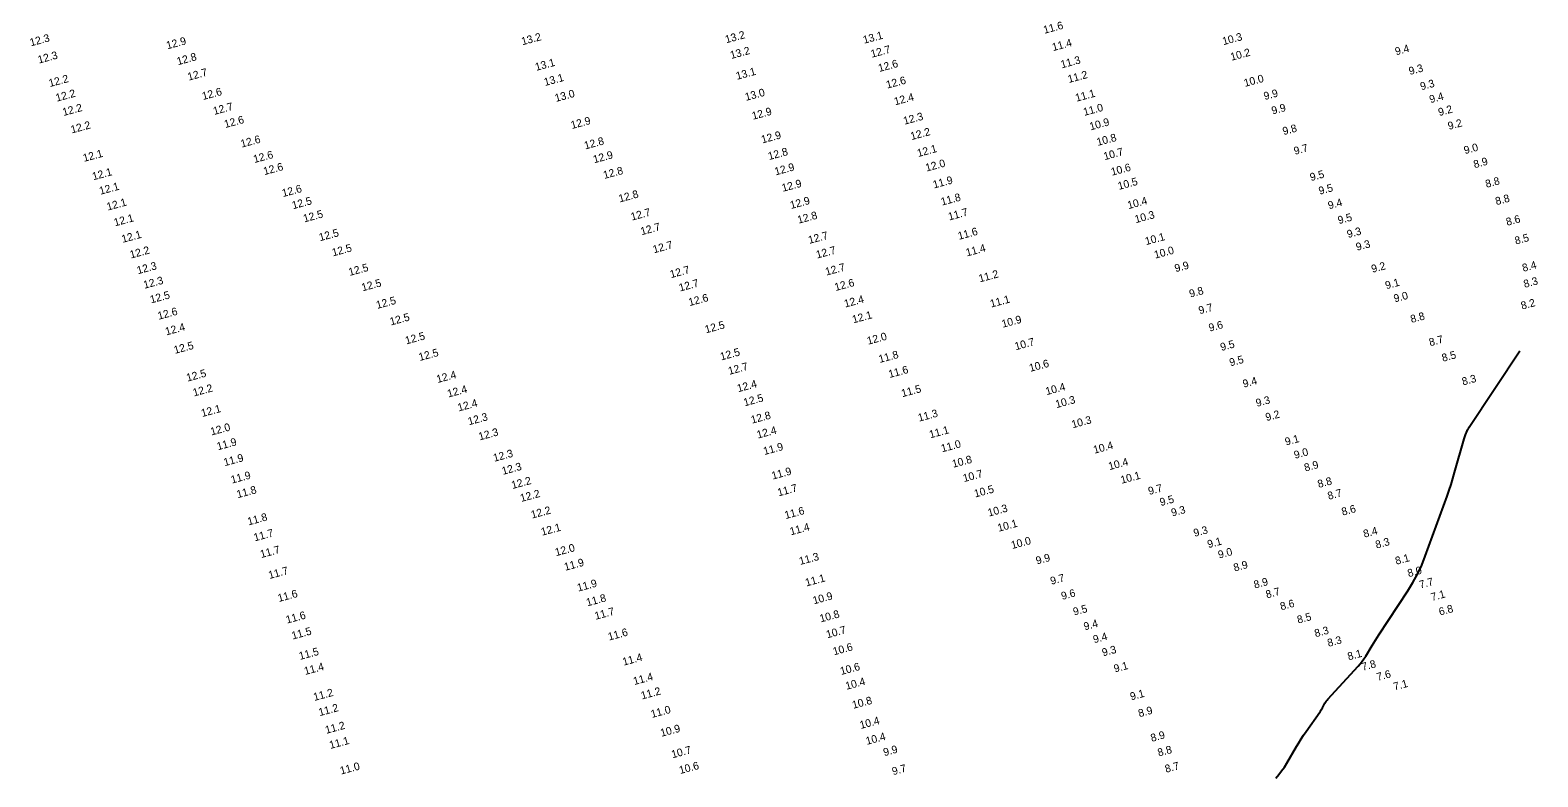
# Model space of a CAD drawing. Extents: x 988130 to 1132882, y 654656 to 841453.
# Drawn here: x 1106374.2 to 1106861.8, y 697159.6 to 697401.1 of the extents above; entities that cross this region are included whole.
import ezdxf

# ---------------------------------------------------------------- set-up
doc = ezdxf.new("R2010")
doc.units = 0
doc.layers.add('V-TOPO-MAJR', color=7, linetype='Continuous')
doc.layers.add('V-TOPO-SOUN', color=7, linetype='Continuous')

msp = doc.modelspace()

# ---------------------------------------------------------------- linework, layer by layer
at = {"layer": 'V-TOPO-MAJR'}
msp.add_lwpolyline([(1106777.02, 697159.2), (1106778.02, 697160.34), (1106778.95, 697161.53), (1106779.82, 697162.77), (1106780.62, 697164.06), (1106783.79, 697169.47), (1106784.52, 697170.68), (1106785.28, 697171.88), (1106786.05, 697173.07), (1106786.85, 697174.24), (1106791.25, 697180.55), (1106791.48, 697180.9), (1106791.7, 697181.25), (1106791.92, 697181.6), (1106792.12, 697181.96), (1106792.92, 697183.42), (1106793.13, 697183.78), (1106793.37, 697184.12), (1106793.62, 697184.45), (1106793.89, 697184.77), (1106803.69, 697195.46), (1106804.35, 697196.22), (1106804.98, 697197.01), (1106805.57, 697197.83), (1106806.12, 697198.68), (1106808.25, 697202.14), (1106808.78, 697203.01), (1106809.32, 697203.86), (1106809.87, 697204.72), (1106810.42, 697205.57), (1106819.76, 697219.76), (1106821.42, 697222.45), (1106822.91, 697225.23), (1106824.24, 697228.08), (1106825.4, 697231.02), (1106832.45, 697250.44), (1106833.12, 697252.32), (1106833.75, 697254.22), (1106834.34, 697256.13), (1106834.9, 697258.05), (1106837.96, 697268.93), (1106838.06, 697269.26), (1106838.17, 697269.59), (1106838.29, 697269.92), (1106838.42, 697270.24), (1106838.97, 697271.52), (1106839.11, 697271.84), (1106839.27, 697272.15), (1106839.44, 697272.45), (1106839.62, 697272.74), (1106856.03, 697297.42)], dxfattribs=at)

# ---------------------------------------------------------------- texts
at = {"layer": 'V-TOPO-SOUN'}
for s, p in [('11.6 ', (1106702.23, 697399.94)), ('12.3 ', (1106374.4, 697395.87)), ('12.9 ', (1106418.55, 697394.92)), ('13.2 ', (1106533.4, 697396.23)), ('13.2 ', (1106599.31, 697396.88)), ('13.1 ', (1106643.9, 697396.72)), ('11.4 ', (1106705.05, 697394.34)), ('10.3 ', (1106760.13, 697396.26)), ('12.3 ', (1106376.99, 697390.3)), ('12.8 ', (1106421.95, 697389.78)), ('13.2 ', (1106600.93, 697391.79)), ('12.7 ', (1106646.4, 697392.19)), ('11.3 ', (1106707.82, 697388.76)), ('10.2 ', (1106762.74, 697391.22)), ('9.4', (1106815.97, 697392.97)), ('12.7 ', (1106425.43, 697384.78)), ('13.1 ', (1106537.85, 697387.95)), ('13.1 ', (1106602.81, 697385.06)), ('12.6 ', (1106648.81, 697387.59)), ('11.2 ', (1106710.13, 697384.02)), ('9.3', (1106820.43, 697386.61)), ('12.2 ', (1106380.53, 697382.71)), ('13.1 ', (1106540.7, 697383.06)), ('12.6 ', (1106651.37, 697382.2)), ('10.0 ', (1106767.09, 697382.77)), ('9.3', (1106824.11, 697381.66)), ('12.2 ', (1106382.78, 697377.98)), ('12.6 ', (1106430.12, 697378.52)), ('12.7 ', (1106433.71, 697373.7)), ('13.0 ', (1106544.22, 697377.9)), ('13.0 ', (1106605.73, 697378.25)), ('12.4 ', (1106653.95, 697376.8)), ('11.1 ', (1106712.57, 697377.96)), ('9.9', (1106773.5, 697378.51)), ('9.4', (1106827.08, 697377.5)), ('12.2 ', (1106384.97, 697373.35)), ('12.6 ', (1106437.28, 697369.45)), ('12.9 ', (1106549.39, 697369.14)), ('12.9 ', (1106607.96, 697372.13)), ('12.3 ', (1106656.94, 697370.52)), ('11.0 ', (1106715.14, 697373.39)), ('9.9', (1106776.02, 697373.83)), ('9.2', (1106829.93, 697373.33)), ('12.2 ', (1106387.64, 697367.71)), ('12.9 ', (1106610.98, 697364.48)), ('12.2 ', (1106659.24, 697365.55)), ('10.9 ', (1106717.15, 697368.7)), ('9.8', (1106779.61, 697367.17)), ('9.2', (1106833.05, 697368.86)), ('12.6 ', (1106442.59, 697363.12)), ('12.8 ', (1106553.71, 697362.54)), ('12.8 ', (1106613.18, 697359.1)), ('12.1 ', (1106661.39, 697360.08)), ('10.8 ', (1106719.46, 697363.67)), ('10.7 ', (1106721.69, 697359.06)), ('9.7', (1106783.23, 697360.78)), ('9.0', (1106838.24, 697361.01)), ('12.1 ', (1106391.6, 697358.52)), ('12.6 ', (1106446.71, 697358.14)), ('12.6 ', (1106449.95, 697354.23)), ('12.9 ', (1106556.6, 697358.06)), ('12.0 ', (1106664.09, 697355.37)), ('8.9', (1106841.35, 697356.46)), ('12.1 ', (1106394.6, 697352.56)), ('12.8 ', (1106559.87, 697352.99)), ('12.9 ', (1106615.29, 697354.14)), ('11.9 ', (1106666.5, 697349.91)), ('10.6 ', (1106724.09, 697354.04)), ('10.5 ', (1106726.32, 697349.45)), ('9.5', (1106788.45, 697352.3)), ('8.8', (1106845.2, 697350.12)), ('12.1 ', (1106396.88, 697347.88)), ('12.6 ', (1106455.97, 697347.14)), ('12.8 ', (1106564.86, 697345.39)), ('12.9 ', (1106617.62, 697348.83)), ('9.5', (1106791.28, 697347.88)), ('12.1 ', (1106399.27, 697342.76)), ('12.5 ', (1106459.2, 697343.2)), ('12.9 ', (1106620.3, 697343.27)), ('11.8 ', (1106669.08, 697344.37)), ('11.7 ', (1106671.43, 697339.56)), ('10.4 ', (1106729.42, 697343.23)), ('9.4', (1106794.29, 697343.17)), ('8.8', (1106848.42, 697344.52)), ('12.1 ', (1106401.6, 697337.66)), ('12.5 ', (1106462.85, 697338.94)), ('12.7 ', (1106568.78, 697339.51)), ('12.7 ', (1106571.94, 697334.79)), ('12.8 ', (1106622.69, 697338.51)), ('10.3 ', (1106731.79, 697338.69)), ('9.5', (1106797.45, 697338.38)), ('8.6', (1106851.88, 697337.83)), ('12.1 ', (1106404.09, 697332.32)), ('12.5 ', (1106467.93, 697332.86)), ('12.7 ', (1106626.19, 697331.99)), ('11.6 ', (1106674.58, 697333.3)), ('10.1 ', (1106735.12, 697331.59)), ('9.3', (1106800.43, 697333.88)), ('8.5', (1106854.68, 697331.76)), ('12.2 ', (1106406.74, 697327.25)), ('12.5 ', (1106472.14, 697327.95)), ('12.7 ', (1106575.92, 697328.94)), ('12.7 ', (1106628.7, 697327.24)), ('11.4 ', (1106677.15, 697327.93)), ('10.0 ', (1106738.05, 697327.21)), ('9.3', (1106803.33, 697329.75)), ('12.3 ', (1106409.04, 697322.18)), ('12.5 ', (1106477.5, 697321.63)), ('12.7 ', (1106581.44, 697320.91)), ('12.7 ', (1106631.7, 697321.74)), ('9.9', (1106744.68, 697322.84)), ('9.2', (1106808.31, 697322.64)), ('8.4', (1106857.11, 697322.96)), ('12.3 ', (1106411.15, 697317.47)), ('12.5 ', (1106481.69, 697316.65)), ('12.7 ', (1106584.35, 697316.58)), ('12.6 ', (1106634.69, 697316.74)), ('11.2 ', (1106681.31, 697319.54)), ('9.1', (1106812.79, 697317.31)), ('8.3', (1106857.55, 697317.77)), ('12.5 ', (1106413.29, 697312.74)), ('12.5 ', (1106486.43, 697310.96)), ('12.6 ', (1106587.45, 697311.86)), ('12.4 ', (1106637.79, 697311.39)), ('11.1 ', (1106685, 697311.39)), ('9.8', (1106749.41, 697314.62)), ('9.0', (1106815.55, 697313.06)), ('12.6 ', (1106415.76, 697307.45)), ('12.5 ', (1106490.84, 697305.6)), ('12.1 ', (1106640.42, 697306.29)), ('9.7', (1106752.43, 697309.22)), ('8.8', (1106820.96, 697306.41)), ('8.2', (1106856.7, 697310.72)), ('12.4 ', (1106418.21, 697302.39)), ('12.5 ', (1106592.75, 697303.06)), ('10.9 ', (1106688.75, 697304.86)), ('9.6', (1106755.71, 697303.6)), ('12.5 ', (1106420.98, 697296.41)), ('12.5 ', (1106495.82, 697299.48)), ('12.0 ', (1106645.19, 697299.37)), ('10.7 ', (1106692.96, 697297.59)), ('9.5', (1106759.46, 697297.35)), ('8.7', (1106826.97, 697298.89)), ('12.5 ', (1106500.18, 697294.12)), ('12.5 ', (1106597.68, 697294.29)), ('11.8 ', (1106648.96, 697293.48)), ('9.5', (1106762.4, 697292.38)), ('8.5', (1106831.1, 697293.86)), ('12.5 ', (1106425.05, 697287.44)), ('12.4 ', (1106505.93, 697286.98)), ('12.7 ', (1106600.29, 697289.64)), ('11.6 ', (1106652.13, 697288.61)), ('10.6 ', (1106697.64, 697290.6)), ('12.2 ', (1106427.15, 697282.64)), ('12.4 ', (1106509.44, 697282.31)), ('12.4 ', (1106603.16, 697284.01)), ('11.5 ', (1106656.29, 697282.41)), ('10.4 ', (1106702.93, 697283.06)), ('9.4', (1106766.73, 697285.48)), ('8.3', (1106837.61, 697286.21)), ('12.4 ', (1106512.78, 697277.8)), ('12.5 ', (1106605.25, 697279.45)), ('10.3 ', (1106706.13, 697278.87)), ('9.3', (1106770.94, 697279.27)), ('12.1 ', (1106429.82, 697275.99)), ('12.3 ', (1106516.1, 697273.34)), ('12.8 ', (1106607.64, 697273.84)), ('11.3 ', (1106661.67, 697274.49)), ('10.3 ', (1106711.36, 697272.35)), ('9.2', (1106774.06, 697274.67)), ('12.0 ', (1106432.83, 697270.02)), ('12.3 ', (1106519.54, 697268.42)), ('12.4 ', (1106609.53, 697269.02)), ('11.1 ', (1106665.3, 697269.1)), ('11.9 ', (1106434.89, 697265.24)), ('11.9 ', (1106611.66, 697263.7)), ('11.0 ', (1106669.14, 697264.58)), ('10.4 ', (1106718.39, 697264.12)), ('9.1', (1106780.37, 697266.75)), ('9.0', (1106783.29, 697262.47)), ('11.9 ', (1106437.1, 697260.1)), ('12.3 ', (1106524.28, 697261.52)), ('12.3 ', (1106527.07, 697257.28)), ('10.8 ', (1106672.71, 697259.58)), ('10.4 ', (1106723.26, 697258.81)), ('8.9', (1106786.6, 697258.36)), ('11.9 ', (1106439.44, 697254.46)), ('12.2 ', (1106530.17, 697252.71)), ('11.9 ', (1106614.33, 697255.76)), ('10.7 ', (1106676.21, 697254.95)), ('10.1 ', (1106727.2, 697254.4)), ('8.8', (1106790.94, 697253.06)), ('11.8 ', (1106441.31, 697249.74)), ('12.2 ', (1106533.01, 697248.52)), ('11.7 ', (1106616.23, 697250.33)), ('10.5 ', (1106679.83, 697249.96)), ('9.7', (1106736.13, 697250.78)), ('8.7', (1106794.17, 697249.22)), ('12.2 ', (1106536.5, 697243.14)), ('11.6 ', (1106618.53, 697242.99)), ('10.3 ', (1106684.24, 697243.78)), ('9.5', (1106739.88, 697247.19)), ('9.3', (1106743.56, 697243.8)), ('8.6', (1106798.68, 697244.09)), ('11.8 ', (1106444.81, 697240.94)), ('12.1 ', (1106539.75, 697237.6)), ('11.4 ', (1106620.22, 697237.73)), ('10.1 ', (1106687.41, 697238.88)), ('11.7 ', (1106446.82, 697235.78)), ('10.0 ', (1106691.79, 697233.29)), ('9.3', (1106750.79, 697237.23)), ('9.1', (1106755.28, 697233.59)), ('8.4', (1106805.71, 697236.96)), ('8.3', (1106809.62, 697233.44)), ('11.7 ', (1106448.91, 697230.38)), ('12.0 ', (1106544.28, 697230.99)), ('11.3 ', (1106623.23, 697228.14)), ('9.9', (1106699.8, 697228.29)), ('9.0', (1106758.73, 697230.2)), ('8.1', (1106816.03, 697228.21)), ('11.7 ', (1106451.58, 697223.6)), ('11.9 ', (1106547.23, 697226.26)), ('8.9', (1106763.73, 697226.02)), ('8.0', (1106820.02, 697224.2)), ('11.9 ', (1106551.43, 697219.52)), ('11.1 ', (1106625.23, 697221.2)), ('9.7', (1106704.48, 697221.72)), ('8.9', (1106770.28, 697220.51)), ('7.7', (1106823.79, 697220.5)), ('11.6 ', (1106454.6, 697216.16)), ('11.8 ', (1106554.38, 697214.76)), ('10.9 ', (1106627.64, 697215.4)), ('9.6', (1106707.98, 697216.84)), ('8.7', (1106774.16, 697217.33)), ('8.6', (1106778.82, 697213.48)), ('7.1', (1106827.58, 697216.49)), ('11.6 ', (1106457.23, 697209.18)), ('11.7 ', (1106557.1, 697210.42)), ('10.8 ', (1106629.87, 697209.56)), ('9.5', (1106711.84, 697211.77)), ('8.5', (1106784.3, 697209.17)), ('6.8', (1106830.15, 697211.77)), ('11.5 ', (1106459.09, 697204.03)), ('11.6 ', (1106561.41, 697203.69)), ('10.7 ', (1106631.98, 697204.42)), ('9.4', (1106715.28, 697206.99)), ('8.3', (1106789.92, 697204.78)), ('10.6 ', (1106634.16, 697198.92)), ('9.4', (1106718.31, 697202.81)), ('8.3', (1106794.1, 697201.66)), ('11.5 ', (1106461.46, 697197.43)), ('11.4 ', (1106566.11, 697195.57)), ('9.3', (1106721.2, 697198.57)), ('8.1', (1106800.62, 697197.3)), ('7.8', (1106805.18, 697193.92)), ('11.4 ', (1106463.13, 697192.57)), ('11.4 ', (1106569.58, 697189.31)), ('10.6 ', (1106636.5, 697192.56)), ('9.1', (1106725.01, 697193.36)), ('7.6', (1106810.01, 697190.66)), ('11.2 ', (1106466.12, 697184.17)), ('11.2 ', (1106572.07, 697184.65)), ('10.4 ', (1106638.22, 697187.76)), ('9.1', (1106730.28, 697184.35)), ('7.1', (1106815.47, 697187.56)), ('11.2 ', (1106467.81, 697179.25)), ('11.0 ', (1106575.27, 697178.66)), ('10.8 ', (1106640.4, 697181.62)), ('10.4 ', (1106642.83, 697175.1)), ('8.9', (1106732.93, 697178.9)), ('11.2 ', (1106469.95, 697173.53)), ('10.9 ', (1106578.36, 697172.57)), ('10.4 ', (1106644.79, 697169.95)), ('8.9', (1106736.93, 697170.93)), ('11.1 ', (1106471.29, 697168.64)), ('10.7 ', (1106581.92, 697165.61)), ('9.9', (1106650.46, 697166.3)), ('8.8', (1106739.19, 697166.2)), ('11.0 ', (1106474.73, 697160.36)), ('10.6 ', (1106584.42, 697160.52)), ('9.7', (1106653.29, 697160.15)), ('8.7', (1106741.55, 697160.93))]:
    msp.add_text(s, height=2.5, rotation=15, dxfattribs=at).set_placement(p)

doc.saveas('drawing.dxf')
